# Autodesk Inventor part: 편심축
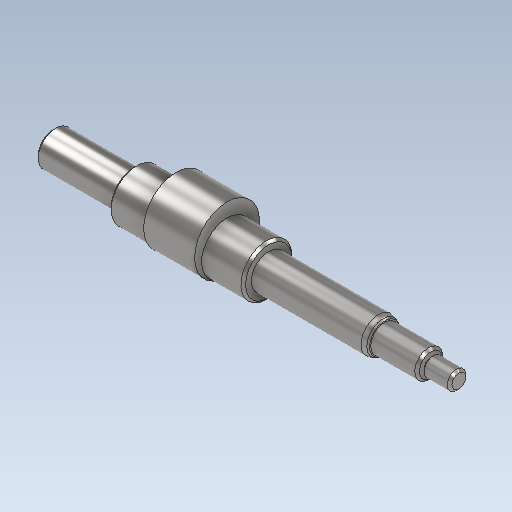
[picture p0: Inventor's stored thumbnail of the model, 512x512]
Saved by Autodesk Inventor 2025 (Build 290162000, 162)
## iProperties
Created: 2024-07
Part Number: 편심축
Material: 강철, 연강
Document SubType Name: Modeling
Designer: 미서니
Density: 7.86 g/cm^3
Appearance: 기본값
Author: jhkim
Sending System: Autodesk Inventor 2025
Preprocessor: ST-DEVELOPER v20
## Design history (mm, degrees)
feature "솔리드1"
node "솔리드2"
